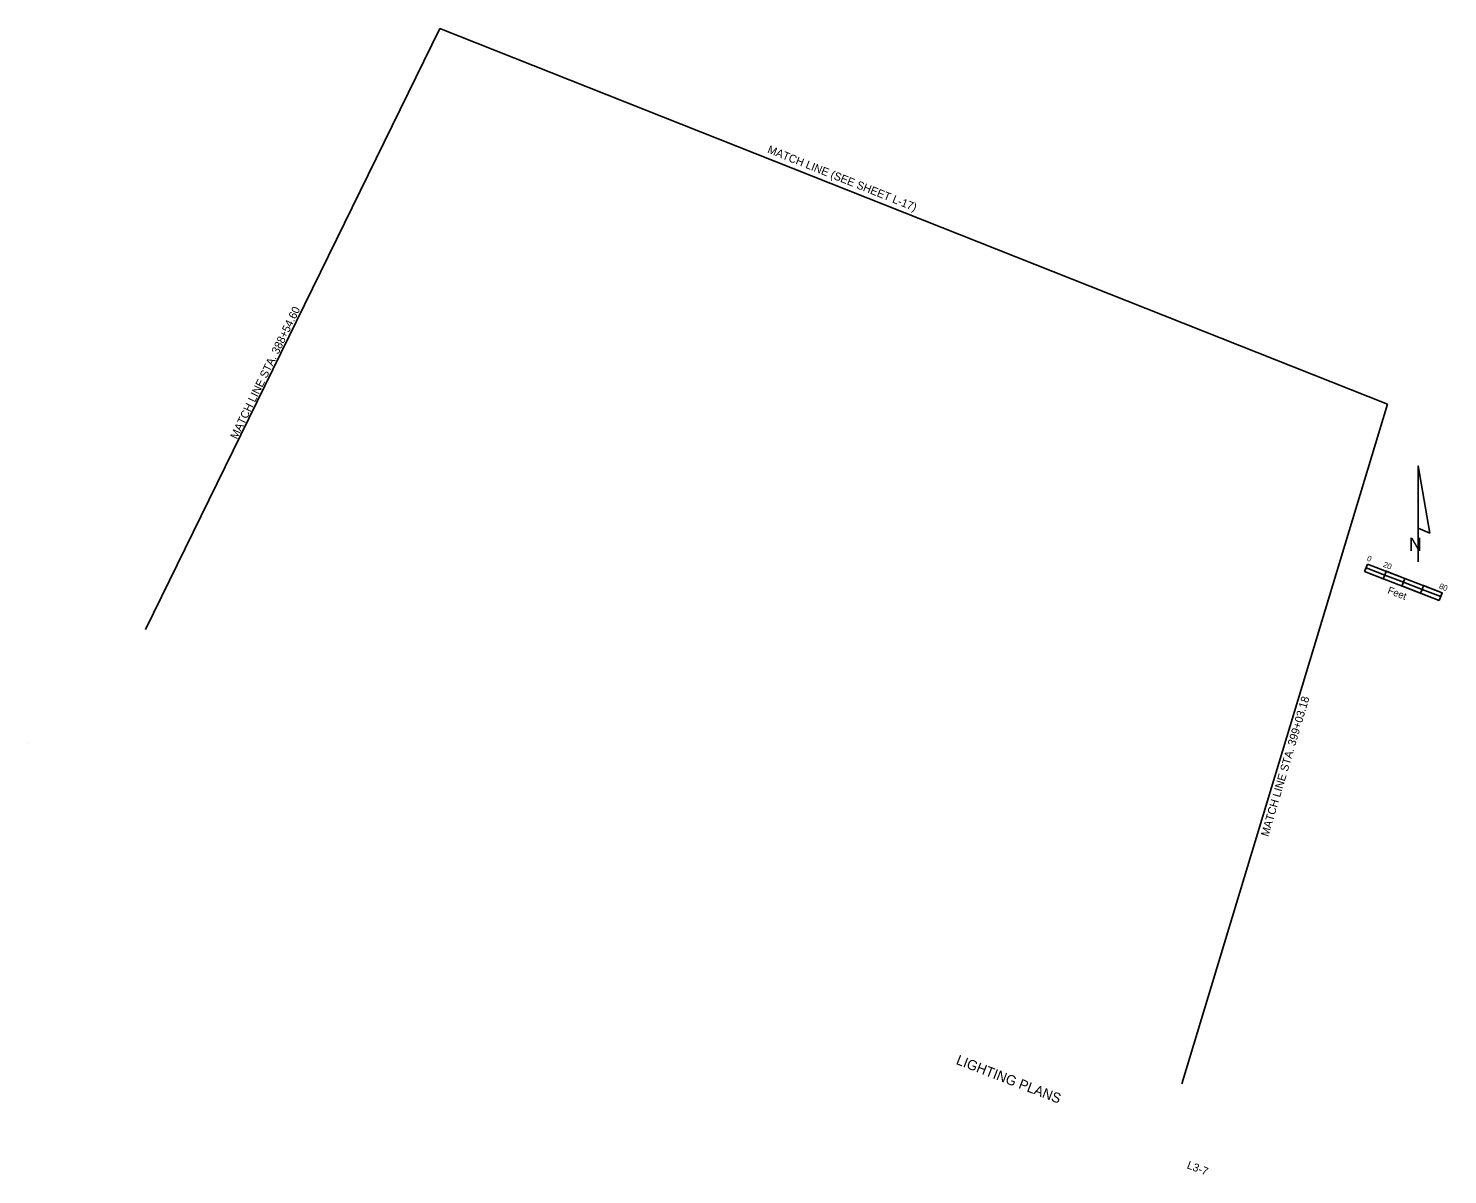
# Model space of a CAD drawing. Extents: x 917028 to 918447, y 636618 to 637764.
import ezdxf

# ---------------------------------------------------------------- set-up
doc = ezdxf.new("R2010")
doc.units = 0
for name, color, linetype in [('AdhocPoint_dp', 7, 'Continuous'), ('MatchLines_dp', 7, 'Continuous'), ('NorthArw_dp', 7, 'Continuous'), ('Scale_dp', 7, 'Continuous'), ('TextMisc', 7, 'Continuous'), ('TextShtNo', 7, 'Continuous')]:
    doc.layers.add(name, color=color, linetype=linetype)

msp = doc.modelspace()

# ---------------------------------------------------------------- linework, layer by layer
at = {"layer": 'AdhocPoint_dp'}
msp.add_line((917028.4, 637048.3), (917028.4, 637048.3), dxfattribs=at)
at = {"layer": 'MatchLines_dp'}
for p, q in [((917145.6, 637162.5), (917439.7, 637763.8)), ((917439.7, 637763.8), (918387, 637388)), ((918387, 637388), (918181.5, 636708.2))]:
    msp.add_line(p, q, dxfattribs=at)
at = {"layer": 'NorthArw_dp'}
msp.add_line((918417.8, 637230.3), (918417.8, 637326.3), dxfattribs=at)
msp.add_lwpolyline([(918417.8, 637263.9), (918417.8, 637326.3), (918429.3, 637259.1)], close=True, dxfattribs=at)
at = {"layer": 'Scale_dp'}
for p, q in [((918367.1, 637228.1), (918364.3, 637220.6)), ((918364.3, 637220.6), (918438.9, 637191.8)), ((918441.8, 637199.3), (918367.1, 637228.1)), ((918438.9, 637191.8), (918441.8, 637199.3))]:
    msp.add_line(p, q, dxfattribs=at)
for points in [[(918364.3, 637220.6), (918365.7, 637224.3), (918384.4, 637217.1), (918382.9, 637213.4)], [(918384.4, 637217.1), (918385.8, 637220.9), (918404.5, 637213.7), (918403, 637209.9)], [(918401.6, 637206.2), (918403, 637209.9), (918421.7, 637202.7), (918420.2, 637199)], [(918421.7, 637202.7), (918423.1, 637206.5), (918441.8, 637199.3), (918440.3, 637195.5)]]:
    msp.add_lwpolyline(points, close=True, dxfattribs=at)

# ---------------------------------------------------------------- texts
at = {"layer": 'MatchLines_dp'}
for s, rotation, p in [('MATCH LINE (SEE SHEET L-17)', 338.2871, (917766.6, 637639.6)), ('MATCH LINE STA. 388+54.60', 64.1323, (917237, 637352.3)), ('MATCH LINE STA. 399+03.18', 73.5485, (918268, 636955))]:
    msp.add_text(s, height=8, rotation=rotation, dxfattribs=at).set_placement(p)
at = {"layer": 'NorthArw_dp'}
msp.add_text('N', height=13.4, dxfattribs=at).set_placement((918408.6, 637241.1))
at = {"layer": 'Scale_dp'}
for s, height, p in [('0', 5.6, (918366.1, 637231.7)), ('20', 5.6, (918382.3, 637225.5)), ('Feet', 7.2, (918386.6, 637199.1)), ('80', 5.6, (918438.2, 637203.9))]:
    msp.add_text(s, height=height, rotation=338.8881, dxfattribs=at).set_placement(p)
at = {"layer": 'TextMisc'}
msp.add_text('        LIGHTING PLANS         ', height=10, rotation=338.8881, dxfattribs=at).set_placement((917927.4, 636739))
at = {"layer": 'TextShtNo'}
msp.add_text(' L3-7 ', height=8, rotation=338.8881, dxfattribs=at).set_placement((918183.2, 636625.2))

doc.saveas('drawing.dxf')
